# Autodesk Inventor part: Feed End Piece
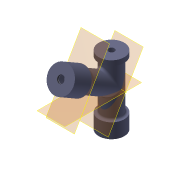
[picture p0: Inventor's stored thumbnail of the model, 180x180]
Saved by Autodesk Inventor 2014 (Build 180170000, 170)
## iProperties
Created: 2016-11
Part Number: Feed End Piece
Material: ABS Plastic
Document SubType Name: Modeling
Designer: Warren
Density: 1.06 g/cm^3
Appearance: Slate Blue
Author: Warren
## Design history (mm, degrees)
sketch "Sketch1"
  geometry: C1 r 1 at (0, 0); 1 further point
  constraints: 1 centre point, 1 coincident
  dimensions: "d0" = 2 diameter of C1
extrude "Extrusion1" new body sketch "Sketch1" stored distance "d1" = 5; taper "d2" = 0 deg
sketch "Sketch2"
  geometry: C1 r 1 at (0, 0) reference; C2 r 1.3 at (0, 0)
  constraints: 1 centre point, 1 coincident
  dimensions: "d10" = 2.6 diameter of C2
extrude "Extrusion2" join sketch "Sketch2" distance "d3" = 0.5; taper "d4" = 0 deg
mirror "Mirror1"
workplane "Work Plane2"
  workplane "Work Plane1"
sketch "Sketch3"
  geometry: C1 r 1 at (0, 0); 1 further point
  constraints: 1 centre point, 1 coincident
  dimensions: "d7" = 2 diameter of C1
extrude "Extrusion3" join sketch "Sketch3" stored distance "d8" = 10; taper "d9" = 0 deg
sketch "Sketch4"
  geometry: C1 r 1 at (0, 0) reference; C2 r 1.3 at (0, 0)
  constraints: 1 centre point, 1 coincident
  dimensions: "d11" = 2.6 diameter of C2
extrude "Extrusion4" join sketch "Sketch4" distance "d12" = 2; taper "d13" = 0 deg
shell "Shell1" dims "d14" = 0.25
sketch "Sketch6"
  geometry: C1 r 1.3 at (0, 0) reference; C2 r 0.3 at (0, 0)
  constraints: 1 centre point, 1 coincident
  dimensions: "d15" = 0.6 diameter of C2
extrude "Extrusion5" cut sketch "Sketch6" stored distance "d16" = 2; taper "d17" = 0 deg
fillet "Fillet1" dims "d18" = 0.2
sketch "Sketch7"
  geometry: C1 r 1.3 at (0, 0) reference; 1 further point
  constraints: 1 coincident
hole "Hole1" sketch "Sketch7" at (0, 0) diameter "d19" = 0.729; stored, may be unused: countersink angle "d23" = 90 deg, drill point angle "d25" = 118 deg; dims "d20" = 6, "d21" = 4, "d22" = 2, "d24" = 1
fillet "Fillet3" dims "d27" = 1
thread "Thread1" dims "d28" = 10, "d29" = 0
thicken "Thicken1" dims "d30" = 1, "d31" = 1
fillet "Fillet4" dims "d32" = 1
body "Solid1"
other parameters: "d5" = 60 deg, "d6" = 4
